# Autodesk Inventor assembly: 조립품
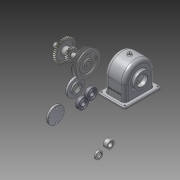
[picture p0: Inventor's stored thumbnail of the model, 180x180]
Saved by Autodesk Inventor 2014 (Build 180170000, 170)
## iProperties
Created: 2016-01
Part Number: 조립품
Document SubType Name: Assembly
Designer: user
Author: user
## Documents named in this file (11)
- C:\Users\user\Desktop\460106V1005\조립품.iam
- C:\Users\user\Desktop\460106V1005\본체.ipt
- C:\Users\user\Desktop\460106V1005\축.ipt
- C:\Users\user\Desktop\460106V1005\V-벨트풀리.ipt
- C:\Users\user\Desktop\460106V1005\뒤커버.ipt
- C:\Users\user\Desktop\460106V1005\앞커버.ipt
- C:\Users\user\Desktop\460106V1005\부시1.ipt
- C:\Users\user\Desktop\460106V1005\부시2.ipt
- C:\Users\user\Desktop\460106V1005\스퍼기어.ipt
- C:\Users\user\Desktop\460106V1005\키 - 6 x 6 x 22.ipt
- C:\Users\user\Desktop\460106V1005\베어링 6203.ipt
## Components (1 placed, 1 different names)
1. V-벨트풀리:1 — Insert:3
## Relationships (1: Insert 1)
- Insert:3: V-벨트풀리:1
